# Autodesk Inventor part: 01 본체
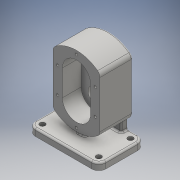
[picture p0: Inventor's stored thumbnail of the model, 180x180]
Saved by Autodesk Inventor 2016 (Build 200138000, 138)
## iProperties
Created: 2022-08
Part Number: 01 본체
Material: 일반
Document SubType Name: Modeling
Designer: 3sil_cad017
Density: 1 g/cm^3
Appearance: 기본값
Mass: 477.11 g
Surface Area: 730.62 cm^2
Volume: 477.11 cm^3
Author: 3sil_cad017
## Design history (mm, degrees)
sketch "스케치1"
  geometry: L1 (0, -22)-(0, 22); L2 (24, -22)-(24, 22); L3 (-24, 22)-(-24, -22); L4 (-40, 44.721)-(-40, -44.721); L5 (40, 44.721)-(40, -44.721); A1 r 24 centre (0, -22) between (-24, -22) and (24, -22); A2 r 24 centre (0, 22) between (24, 22) and (-24, 22); A3 r 60 centre (0, 0) between (40, 44.721) and (-40, 44.721); A4 r 60 centre (0, 0) between (-40, -44.721) and (40, -44.721); 5 further points
  constraints: 12 end point, 8 point on circle, 4 centre point, 4 tangent, 2 coincident, 2 symmetric about line, 2 vertical, 1 concentric, 1 midpoint, 1 parallel, 1 other
  dimensions: "d0" = 44 distance of L1.start L1.end; "d1" = 24 radius of A2; "d2" = 80 distance between parallel lines of L4 L5; "d3" = 60 radius of A3
extrude "돌출1" new body sketch "스케치1" distance "d4" = 56; taper "d5" = 0 deg
node "작업 평면1"
sketch "스케치2"
  geometry: L1 (-60, 56)-(60, 56); L2 (60, 56)-(60, -22); L3 (60, -22)-(-60, -22); L4 (-60, -22)-(-60, 56); L5 (40, 56)-(-40, 56) reference; L6 (40, 0)-(-40, 0) reference; 3 further points
  constraints: 8 end point, 2 midpoint, 2 parallel, 1 horizontal, 1 perpendicular, 1 point on line, 1 vertical alignment
  dimensions: "d7" = 120 distance of L2.end L3.end; "d8" = 78 distance of L1.end L2.end
extrude "돌출2" join sketch "스케치2" distance "d9" = 12; taper "d10" = 0 deg
sketch "스케치3"
  geometry: L1 (32, 0)-(-32, 0); L2 (-32, 0)-(-32, 80); L3 (-32, 80)-(32, 80); L4 (32, 80)-(32, 0); L5 (-60, 80)-(60, 80) reference; 2 further points
  constraints: 8 end point, 2 coincident, 2 parallel, 1 horizontal, 1 midpoint, 1 perpendicular, 1 point on line
  dimensions: "d11" = 64 distance between parallel lines of L2 L4
extrude "돌출3" join sketch "스케치3" distance "d12" = 12; taper "d13" = 0 deg
sketch "스케치4"
  geometry: L1 (8, -55.833)-(8, -66.773); L2 (56, -68)-(56, -50.754) reference; 1 further point
  constraints: 2 end point, 1 vertical
  dimensions: "d14" = 48 distance between parallel lines of L1 L2
feature "리브1" sketch "스케치4" dims "d15" = 1, "d16" = 12, "d17" = 0, "d18" = 0, "d19" = 1, "d20" = 1
fillet "모깎기1" dims "d21" = 12
sketch "스케치5"
  geometry: A1 r 12 centre (-48, 44) between (-48, 56) and (-60, 44) reference; A2 r 12 centre (-48, -10) between (-60, -10) and (-48, -22) reference; A3 r 12 centre (48, -10) between (48, -22) and (60, -10) reference; A4 r 12 centre (48, 44) between (60, 44) and (48, 56) reference; 5 further points
  constraints: 4 coincident
hole "구멍1" sketch "스케치5" at (-48, 44), (48, 44), (48, -10), (-48, -10) diameter "d22" = 9; stored, may be unused: countersink angle "d26" = 90 deg, drill point angle "d28" = 118 deg; dims "d23" = 6, "d24" = 4, "d25" = 2, "d27" = 8
sketch "스케치6"
  geometry: C1 r 19 at (0, -22); 1 further point
  constraints: 1 centre point, 1 vertical alignment
  dimensions: "d29" = 22 distance of C1.centre point (0, 0); "d30" = 38 diameter of C1
extrude "돌출4" join sketch "스케치6" distance "d31" = 12; taper "d32" = 0 deg
extrude "돌출5" cut sketch "스케치1" distance "d33" = 32; taper "d34" = 0 deg
sketch "스케치7"
  geometry: L1 (-24, -22)-(-24, 22) reference; L2 (24, 22)-(24, -22) reference; A1 r 24 centre (0, -22) between (-24, -22) and (24, -22) reference; A2 r 24 centre (0, 22) between (24, 22) and (-24, 22) reference; 3 further points
  constraints: 2 coincident
hole "구멍2" sketch "스케치7" at (0, 22), (0, -22) diameter "d35" = 25; stored, may be unused: countersink angle "d39" = 90 deg, drill point angle "d41" = 0 deg; dims "d36" = 6, "d37" = 4, "d38" = 2, "d40" = 15
sketch "스케치8"
  geometry: C1 r 12.5 at (0, -22) reference; 2 further points
  constraints: 1 coincident
hole "구멍3" sketch "스케치8" at (0, -22) diameter "d42" = 16; stored, may be unused: countersink angle "d46" = 90 deg, drill point angle "d48" = 118 deg; dims "d43" = 6, "d44" = 4, "d45" = 2, "d47" = 15
sketch "스케치9"
  geometry: C1 r 12.5 at (0, 0) reference; 2 further points
  constraints: 1 coincident
hole "구멍4" sketch "스케치9" at (0, 0) diameter "d49" = 17; stored, may be unused: countersink angle "d53" = 90 deg, drill point angle "d55" = 118 deg; dims "d50" = 6, "d51" = 4, "d52" = 2, "d54" = 15
sketch "스케치10"
  geometry: C1 r 8.5 at (0, 0) reference; C2 r 14 at (0, 0); 1 further point
  constraints: 1 centre point, 1 coincident
  dimensions: "d56" = 28 diameter of C2
extrude "돌출6" cut sketch "스케치10" distance "d57" = 8.3; taper "d58" = 0 deg
sketch "스케치11"
  geometry: L1 (-24, -22)-(-24, 22) reference; L2 (24, 22)-(24, -22) reference; L3 (32, 22)-(32, -22); L4 (-32, -22)-(-32, 22); A1 r 24 centre (0, 22) between (24, 22) and (-24, 22) reference; A2 r 24 centre (0, -22) between (-24, -22) and (24, -22) reference; A3 r 32 centre (0, 22) between (32, 22) and (-32, 22); A4 r 32 centre (0, -22) between (-32, -22) and (32, -22); 7 further points
  constraints: 6 point on circle, 4 coincident, 4 end point, 2 centre point, 3 other
  dimensions: "d59" = 32 radius of A3
hole "구멍5" sketch "스케치11" at (-32, 22), (32, 22), (-32, -22), (32, -22), (0, -54), (0, 54) diameter "d60" = 4.134; stored, may be unused: countersink angle "d64" = 90 deg, drill point angle "d66" = 118 deg; dims "d61" = 10, "d62" = 4, "d63" = 2, "d65" = 12
fillet "모깎기2" dims "d67" = 0.5
chamfer "모따기1" distance "d68" = 0.8; stored, may be unused: second distance "d69" = 2, angle "d70" = 30 deg
fillet "모깎기3" dims "d71" = 10
fillet "모깎기4" dims "d72" = 3
fillet "모깎기5" dims "d73" = 3
fillet "모깎기6" dims "d74" = 3
fillet "모깎기7" dims "d75" = 3
node "솔리드1"
node "투영된 루프1"
node "투영된 루프2"
